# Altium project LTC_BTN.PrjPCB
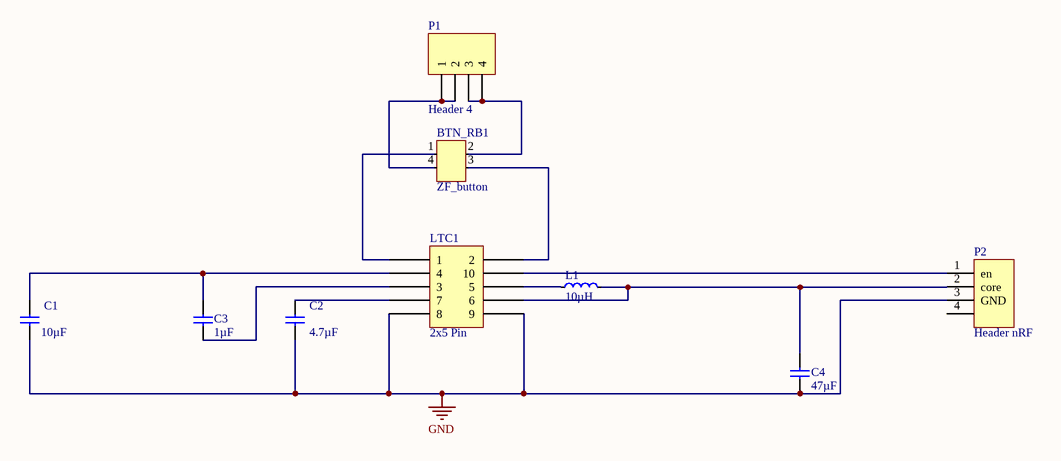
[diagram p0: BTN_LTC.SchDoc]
1 sheet, 9 parts. Net scope: global (net labels, ports and power ports of the same name join across sheets).

## Sheet BTN_LTC.SchDoc
size A4

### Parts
BTN_RB1  ZF_button  [ZF-button]
C1  10µF  [CAPC1608X06L]
C2  4.7µF  [CAPC1608X06L]
C3  1µF  [CAPC1608X06L]
C4  47µF  [CAPC1608X06L]
L1  10µH  [INDC1608X06L]
LTC1  2x5 Pin  [MSOP10 - duplicate]
P1  Header 4  [HDR1X4]
P2  Header nRF  [HDR1X4]

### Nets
GND: C1.1 C2.1 C4.1 LTC1.8 LTC1.9 P2.3(GND)
NetBTN_RB1_1: BTN_RB1.1 LTC1.1
NetBTN_RB1_2: BTN_RB1.2 P1.3 P1.4
NetBTN_RB1_3: BTN_RB1.3 LTC1.2
NetBTN_RB1_4: BTN_RB1.4 P1.1 P1.2
NetC1_2: C1.2 C3.2 LTC1.4
NetC2_2: C2.2 LTC1.7
NetC3_1: C3.1 LTC1.3
NetC4_2: C4.2 L1.2 LTC1.6 P2.2(core)
NetL1_1: L1.1 LTC1.5
NetLTC1_10: LTC1.10 P2.1(en)

Not connected (* = marked no-connect by the designer): P2 4

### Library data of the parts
C1-C4 = CAP_0603: Capacitor, X5R, ±10%; Part Number: C0603-4µ7; Note: 6.3V; Artikkelnr Noca: 20069060; Artikkelnr Simpro: N.A.
L1 = IND_0603: Chip inductor, IDC,min = 50 mA, ±20%; Part Number: L0603-10µ; Manufacturer: Taiyo Yuden; Manufacturer Part Number: LBMF1608T100K; 2nd source part number: 178-6105; Note: LBMF1608T100K 10µH 80mA 0603; Artikkelnr Noca: 33029314; Artikkelnr Simpro: N.A.
P1 P2 = Header 4: Header, 4-Pin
